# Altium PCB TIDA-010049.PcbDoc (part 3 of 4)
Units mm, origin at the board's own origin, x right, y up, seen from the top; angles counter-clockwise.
Board outline 75 x 60 mm, 4 copper layers (Top Layer, GND, Supply, Bottom Layer), stack 1.565 mm thick; 309 components, 186 nets, 995 pads, 362 vias.
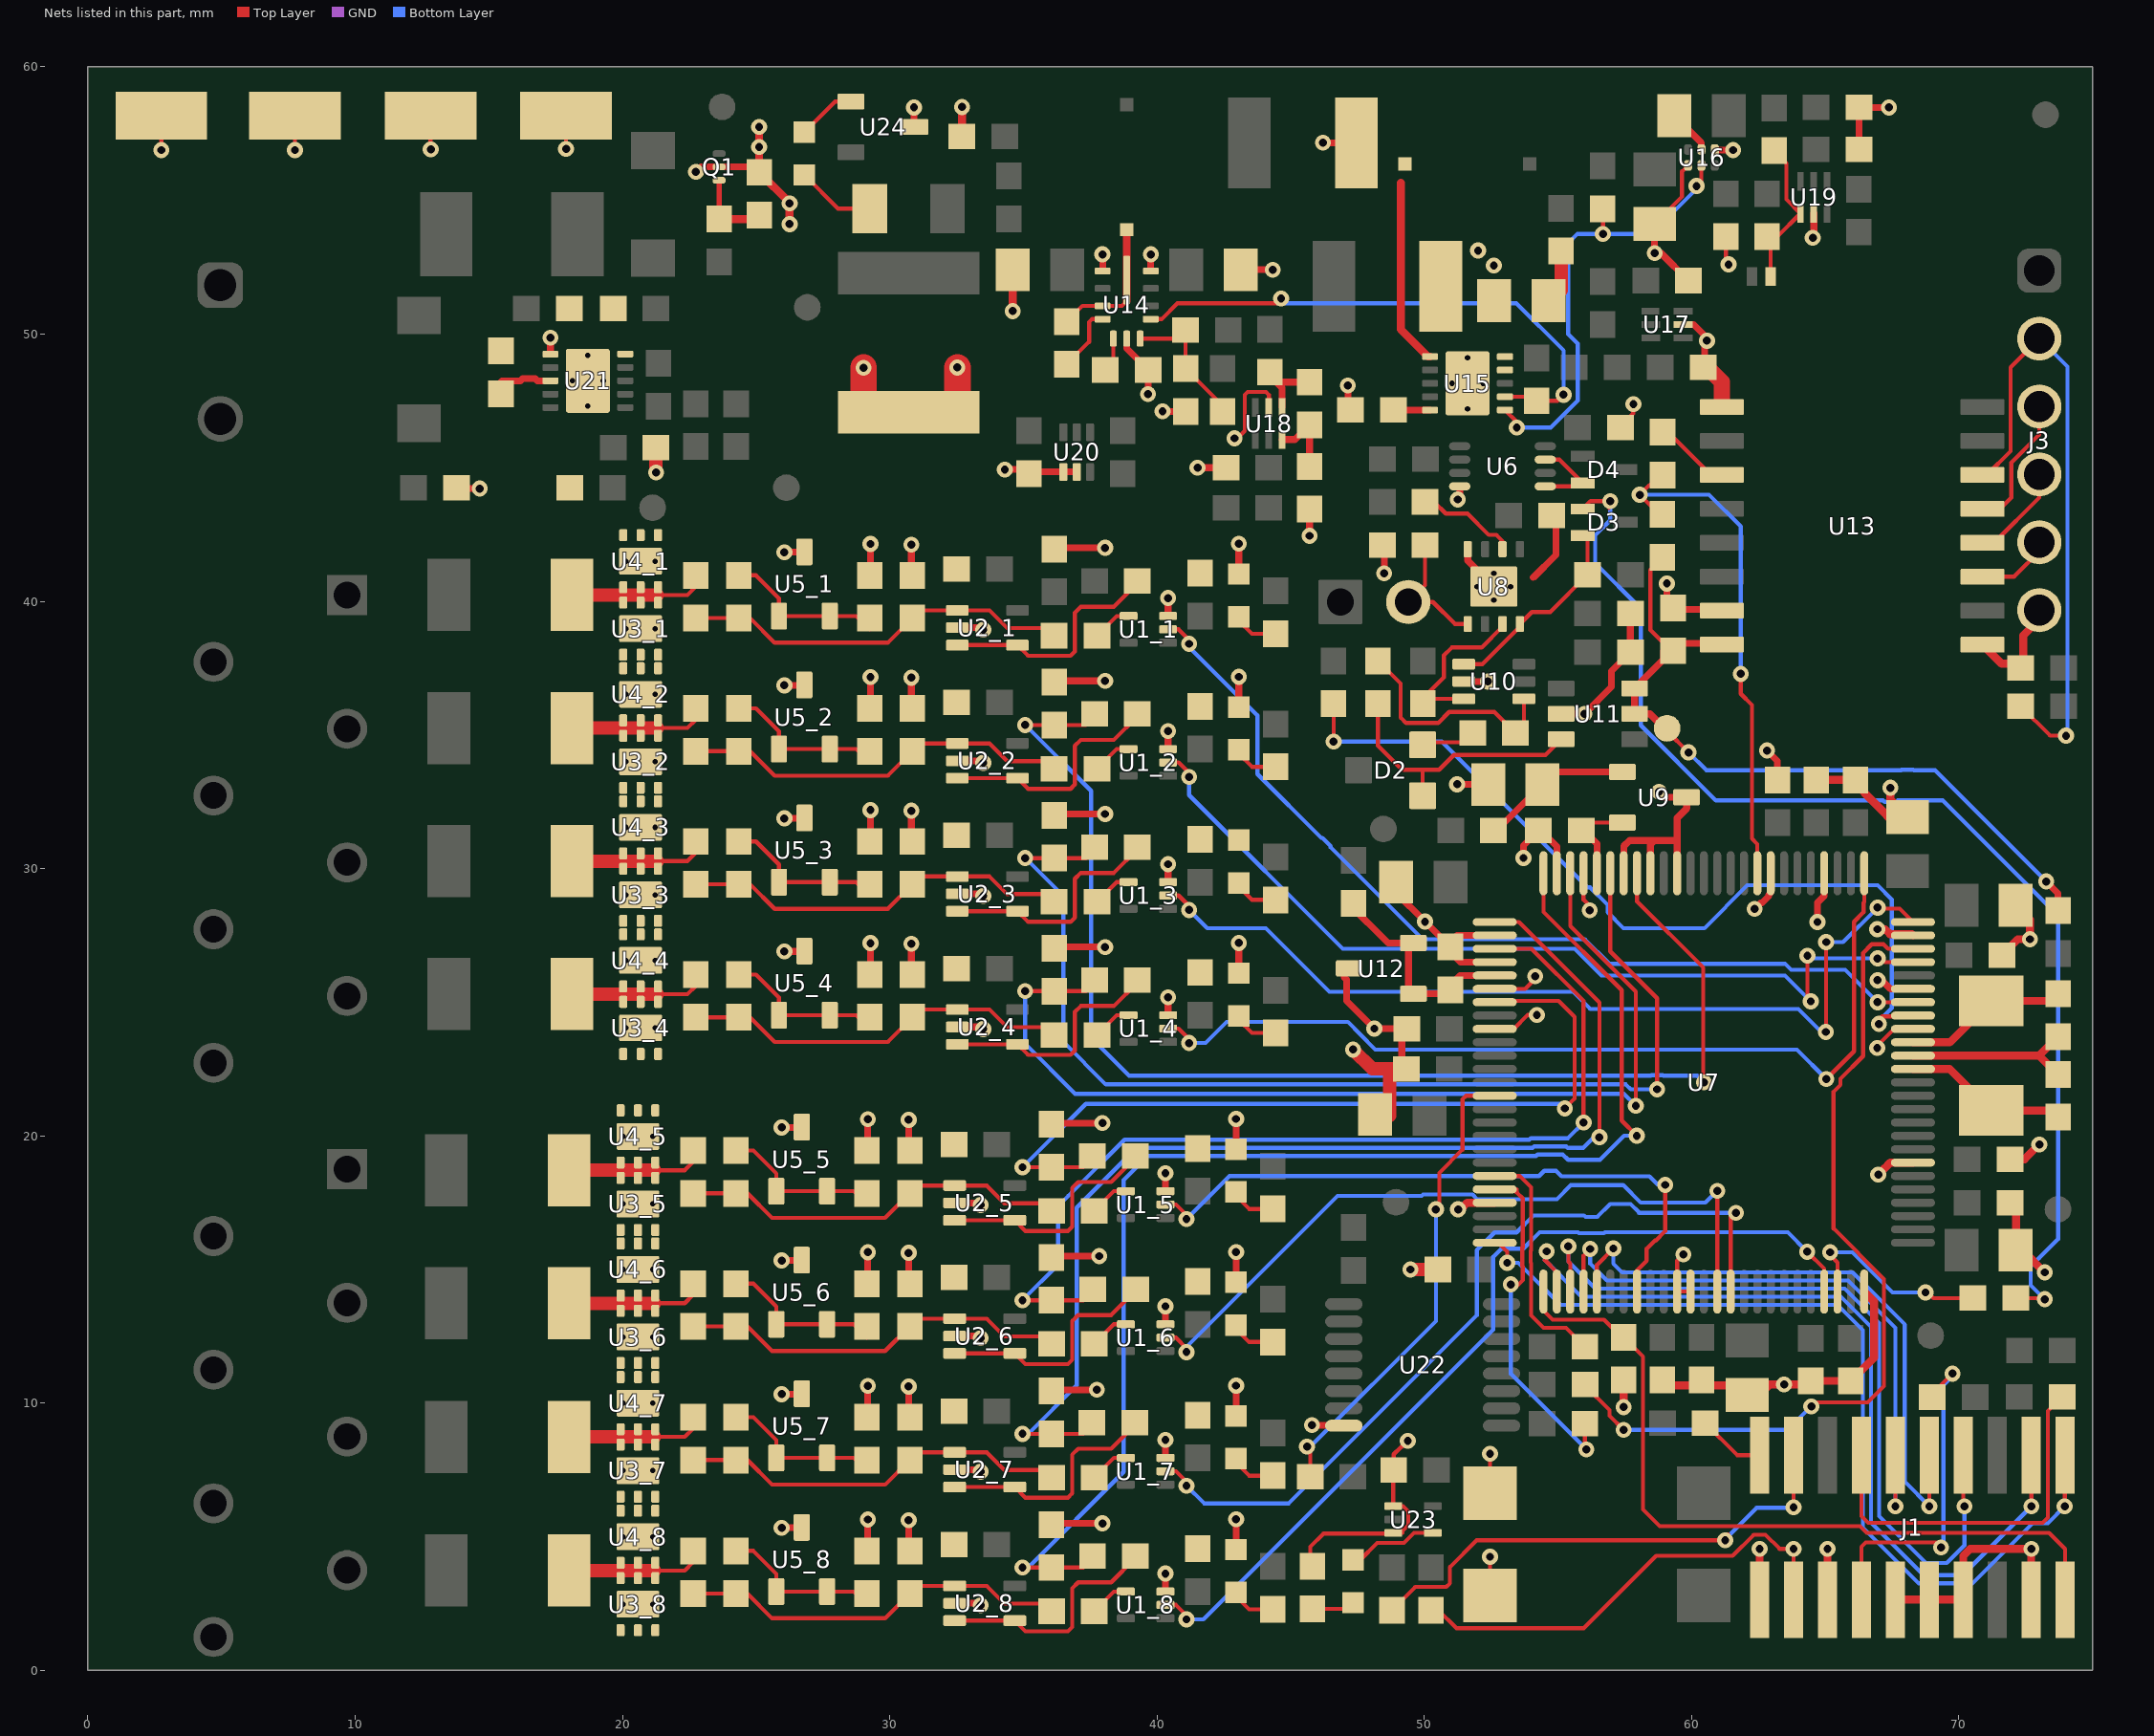
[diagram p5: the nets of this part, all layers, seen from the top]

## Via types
v1: diameter 0.6, hole 0.3, Top Layer to Bottom Layer, 318 vias
v2: diameter 0.5, hole 0.2, Top Layer to Bottom Layer, 44 vias

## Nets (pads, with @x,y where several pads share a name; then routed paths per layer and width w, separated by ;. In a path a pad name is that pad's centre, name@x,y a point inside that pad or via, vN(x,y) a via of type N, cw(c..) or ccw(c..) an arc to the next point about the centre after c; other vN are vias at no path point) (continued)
DI_LOGIC2: C1_2.1 R4_2.2 U7.43 | length 48.5
  Top Layer w0.152: v1(35.07,35.371) C1_2.1@36.152,35.371 37.342,35.371 R4_2.2@37.563,35.592 ; R4_2.2@37.308,35.846 R4_2.2@37.563,35.592 ; R4_2.2@37.667,35.571 37.583,35.571 R4_2.2@37.563,35.592 ; U7.43@57.958,29.825 57.958,28.768 60.429,26.296 60.429,22.028 v1(60.458,22)
  Bottom Layer w0.152: v1@35.277,35.371 v1(35.07,35.371) 37.532,32.909 37.532,23.676 38.958,22.25 58.471,22.25 58.489,22.268 58.927,22.268 58.945,22.25 60.208,22.25 v1(60.458,22)
DI_LOGIC3: C1_3.1 R4_3.2 U7.45 | length 42.5
  Top Layer w0.152: v1(35.07,30.393) C1_3.1@36.152,30.393 37.342,30.393 R4_3.2@37.563,30.614 ; R4_3.2@37.308,30.868 R4_3.2@37.563,30.614 ; R4_3.2@37.667,30.593 37.583,30.593 R4_3.2@37.563,30.614 ; U7.45@56.958,29.825 56.958,26.901 58.708,25.151 v1(58.708,21.74)
  Bottom Layer w0.152: v1@35.277,30.393 v1(35.07,30.393) 36.5,28.963 36.5,23.511 38.085,21.926 57.54,21.926 57.727,21.74 v1(58.708,21.74)
DI_LOGIC4: C1_4.1 R4_4.2 U7.48 | length 38.7
  Top Layer w0.152: v1(35.07,25.414) C1_4.1@36.152,25.414 37.342,25.414 R4_4.2@37.563,25.635 ; R4_4.2@37.308,25.889 R4_4.2@37.563,25.635 ; R4_4.2@37.667,25.614 37.583,25.614 R4_4.2@37.563,25.635 ; U7.48@55.458,29.825 55.458,27.849 57.91,25.396 v1(57.91,21.128)
  Bottom Layer w0.152: v1@35.277,25.414 v1(35.07,25.414) 35.07,23.438 36.934,21.574 57.465,21.574 v1(57.91,21.128)
DI_LOGIC5: C1_5.1 R4_5.2 U7.57 | length 31.5
  Top Layer w0.152: v1(34.969,18.828) C1_5.1@36.052,18.828 37.241,18.828 R4_5.2@37.462,19.049 ; R4_5.2@37.208,19.303 R4_5.2@37.462,19.049 ; R4_5.2@37.566,19.028 37.483,19.028 R4_5.2@37.462,19.049 ; U7.57@52.633,25 52.633,25.052 55.024,25.052 55.626,24.449 55.626,21.397 v1(55.255,21.025)
  Bottom Layer w0.152: v1@35.177,18.828 v1(34.969,18.828) 37.336,21.195 55.085,21.195 v1(55.255,21.025)
DI_LOGIC6: C1_6.1 R4_6.2 U7.53 | length 37
  Top Layer w0.152: v1(34.969,13.85) C1_6.1@36.052,13.85 37.241,13.85 R4_6.2@37.462,14.071 ; R4_6.2@37.208,14.325 R4_6.2@37.462,14.071 ; R4_6.2@37.566,14.05 37.483,14.05 R4_6.2@37.462,14.071 ; U7.53@52.633,27 54.005,27 55.958,25.047 v1(55.958,20.5)
  Bottom Layer w0.152: v1@35.177,13.85 v1(34.969,13.85) 36.302,15.182 36.302,17.372 36.698,17.768 36.698,17.775 36.875,17.952 36.881,17.952 38.784,19.855 53.926,19.855 53.984,19.912 55.37,19.912 v1(55.958,20.5)
DI_LOGIC7: C1_7.1 R4_7.2 U7.51 | length 43.4
  Top Layer w0.152: v1(34.97,8.85) C1_7.1@36.052,8.85 37.241,8.85 R4_7.2@37.462,9.071 ; R4_7.2@37.208,9.325 R4_7.2@37.462,9.071 ; R4_7.2@37.566,9.05 37.483,9.05 R4_7.2@37.462,9.071 ; U7.51@52.633,28 53.537,28 56.55,24.987 v1(56.55,19.95)
  Bottom Layer w0.152: v1(34.97,8.85) 35.177,8.85 37,10.673 37,17.314 39.236,19.55 54.053,19.55 54.11,19.608 55.306,19.608 55.363,19.55 55.941,19.55 56.35,19.958 56.358,19.95 v1(56.55,19.95)
DI_LOGIC8: C1_8.1 R4_8.2 U7.50 | length 50.6
  Top Layer w0.152: v1(34.969,3.85) C1_8.1@36.052,3.85 37.241,3.85 R4_8.2@37.462,4.071 ; R4_8.2@37.208,4.325 R4_8.2@37.462,4.071 ; R4_8.2@37.566,4.05 37.483,4.05 R4_8.2@37.462,4.071 ; U7.50@54.458,29.825 54.458,28.379 57.384,25.453 57.384,20.568 v1(57.948,20.005)
  Bottom Layer w0.152: v1(34.969,3.85) 35.177,3.85 38.75,7.424 38.75,18.345 39.65,19.245 54.179,19.245 54.236,19.303 55.179,19.303 55.379,19.103 56.573,19.103 57.474,20.005 v1(57.948,20.005)
DIAG_CTRL1: U1_1.2 U7.19 | length 35.1
  Top Layer w0.152: U1_1.2@40.415,38.95 40.807,38.95 41.202,38.554 v1(41.202,38.409) ; v1(66.958,25) 67.099,25 U7.19@68.283,25
  Bottom Layer w0.152: v1(41.202,38.409) 41.202,38.287 43.758,35.731 43.758,33.533 46.146,31.145 46.187,31.145 46.497,30.836 46.497,30.795 49.936,27.355 56.003,27.355 56.917,26.441 63.491,26.441 63.721,26.211 65.747,26.211 v1(66.958,25)
DIAG_CTRL2: U1_2.2 U7.22 | length 34.2
  Top Layer w0.152: U1_2.2@40.415,33.971 40.807,33.971 41.202,33.576 v1(41.202,33.43) ; v1(64.333,26.739) 64.333,25.156 v1(64.458,25.031) ; v1(66.958,26.639) 67.077,26.639 67.216,26.5 U7.22@68.283,26.5
  Bottom Layer w0.152: v1(41.202,33.43) 41.202,32.751 46.953,27 55.626,27 56.626,26 63.489,26 v1(64.458,25.031) ; v1@64.208,26.739 v1(64.333,26.739) 64.458,26.739 64.558,26.639 v1(66.958,26.639)
DIAG_CTRL3: U1_3.2 U7.25 | length 34.2
  Top Layer w0.152: U1_3.2@40.415,28.993 40.807,28.993 41.202,28.597 v1(41.202,28.452) ; v1(65.023,23.889) 65.032,23.898 v1(65.032,27.25) ; v1@66.958,28.5 67.783,28.5 U7.25@68.283,28
  Bottom Layer w0.152: v1(41.202,28.452) 41.882,27.772 44.07,27.772 46.453,25.39 55.568,25.39 56.208,24.75 63.991,24.75 64.852,23.889 v1(65.023,23.889) ; v1(65.032,27.25) 65.667,27.25 v1(66.958,28.541)
DIAG_CTRL4: U1_4.2 U7.26 | length 34.4
  Top Layer w0.152: U1_4.2@40.415,24.014 40.807,24.014 41.202,23.619 v1(41.202,23.473) ; v1(65.039,22.128) 66.073,23.162 66.073,28.01 66.429,28.366 66.429,28.719 66.458,28.748 U7.26@66.458,29.825
  Bottom Layer w0.152: v1(41.202,23.473) 41.819,23.473 42.605,24.259 47.141,24.259 47.6,23.8 47.6,23.795 48.167,23.229 63.938,23.229 v1(65.039,22.128)
DIAG_CTRL5: U1_5.2 U7.83 | length 24.4
  Top Layer w0.152: U1_5.2@40.315,17.428 40.706,17.428 41.102,17.033 v1(41.102,16.887) ; U7.83@57.958,14.175 57.958,14.966 58.323,15.331 58.317,15.337 58.317,15.773 58.625,16.081 58.658,16.081 59.009,16.432 v1(59.009,18.165)
  Bottom Layer w0.152: v1(41.102,16.887) 42.708,18.494 54.289,18.494 54.489,18.693 54.927,18.693 55.13,18.491 58.419,18.491 58.745,18.165 v1(59.009,18.165)
DIAG_CTRL6: U1_6.2 U7.89 | length 28
  Top Layer w0.152: U1_6.2@40.315,12.45 40.706,12.45 41.102,12.054 v1(41.102,11.909) ; U7.89@60.958,14.175 v1(60.958,17.942)
  Bottom Layer w0.152: v1(41.102,11.909) 41.102,12.099 46.757,17.754 49.899,17.754 49.95,17.805 51.806,17.805 51.979,17.632 54.958,17.632 55.48,18.154 57.442,18.154 58.096,17.5 60.516,17.5 v1(60.958,17.942)
DIAG_CTRL7: U1_7.2 U7.90 | length 31.1
  Top Layer w0.152: U1_7.2@40.315,7.45 40.707,7.45 41.102,7.055 v1(41.102,6.909) ; U7.90@61.458,14.175 v1@61.458,17.077
  Bottom Layer w0.152: v1(41.102,6.909) 41.761,6.25 44.932,6.25 51.962,13.28 51.962,15.721 52.629,16.388 53.448,16.388 54.082,17.022 55.973,17.022 56.032,16.963 56.468,16.963 56.955,17.45 57.718,17.45 58.026,17.142 58.026,17.115 v1(61.66,17.115)
DIAG_CTRL8: U1_8.2 U7.97 | length 34
  Top Layer w0.152: U1_8.2@40.315,2.45 40.706,2.45 41.102,2.055 v1(41.102,1.909) ; v1(64.323,15.666) 64.958,15.031 U7.97@64.958,14.175
  Bottom Layer w0.152: v1(41.102,1.909) 41.737,1.909 52.571,12.743 52.571,15.469 52.881,15.779 53.7,15.779 54.315,16.394 55.746,16.394 55.782,16.358 56.718,16.358 56.754,16.394 63.595,16.394 v1(64.323,15.666)
DVDD: C28.1 J3.6 U13.1 | length 4.2
  Top Layer w0.3: U13.1@70.883,38.38 71.595,37.668 72.408,37.668 72.408,38.726 J3.6@73.327,39.645
GND: C1_1.2 C1_2.2 C1_3.2 C1_4.2 C1_5.2 C1_6.2 C1_7.2 C1_8.2 C2_1.2 C2_2.2 C2_3.2 C2_4.2 C2_5.2 C2_6.2 C2_7.2 C2_8.2 C3_1.2 C3_2.2 C3_3.2 C3_4.2 C3_5.2 C3_6.2 C3_7.2 C3_8.2 C4_1.2 C4_2.2 C4_3.2 C4_4.2 C4_5.2 C4_6.2 C4_7.2 C4_8.2 C5.2 C6.2 C7.2 C8.2 C9.2 C10.2 C11.2 C12.2 C13.2 C14.2 C15.2 C16.2 C17.2 C18.2 C19.2 C20.2 C21.2 C22.2 C23.2 C24.2 C25.2 C26.2 C27.2 C29.2 C30.2 C33.2 C35.2 C36.2 C37.2 C39.2 C40.2 C41.2 C42.2 C43.2 C44.2 C45.2 C46.2 C47.2 C48.2 C49.2 C50.2 C52.2 C53.2 D1_1.1 D1_2.1 D1_3.1 D1_4.1 D1_5.1 D1_6.1 D1_7.1 D1_8.1 J1.4 J1.8 J1.10 J1.12 J1.16 J1.20 Q1.2@23.616,56.25 R7_1.1 R7_2.1 R7_3.1 R7_4.1 R7_5.1 R7_6.1 R7_7.1 R7_8.1 R17.1 R20.1 R33.2 R34.2 R36.2 R46.2 R47.2 R48.2 R62.2 R64.1 S1.1 S2.1 TP11.1 TP12.1 TP13.1 TP14.1 U1_1.3 U1_2.3 U1_3.3 U1_4.3 U1_5.3 U1_6.3 U1_7.3 U1_8.3 U2_1.2 U2_2.2 U2_3.2 U2_4.2 U2_5.2 U2_6.2 U2_7.2 U2_8.2 U3_1.1 U3_1.2 U3_1.3 U3_1.7@20.681,38.975 U3_2.1 U3_2.2 U3_2.3 U3_2.7@20.681,33.996 U3_3.1 U3_3.2 U3_3.3 U3_3.7@20.681,29.018 U3_4.1 U3_4.2 U3_4.3 U3_4.7@20.681,24.039 U3_5.1 U3_5.2 U3_5.3 U3_5.7@20.581,17.453 U3_6.1 U3_6.2 U3_6.3 U3_6.7@20.581,12.475 U3_7.1 U3_7.2 U3_7.3 U3_7.7@20.581,7.475 U3_8.1 U3_8.2 U3_8.3 U3_8.7@20.581,2.475 U4_1.1 U4_1.2 U4_1.3 U4_1.7@20.681,41.5 U4_2.1 U4_2.2 U4_2.3 U4_2.7@20.681,36.521 U4_3.1 U4_3.2 U4_3.3 U4_3.7@20.681,31.543 U4_4.1 U4_4.2 U4_4.3 U4_4.7@20.681,26.564 U4_5.1 U4_5.2 U4_5.3 U4_5.7@20.581,19.978 U4_6.1 U4_6.2 U4_6.3 U4_6.7@20.581,15 U4_7.1 U4_7.2 U4_7.3 U4_7.7@20.581,10 U4_8.1 U4_8.2 U4_8.3 U4_8.7@20.581,5 U5_1.3 U5_2.3 U5_3.3 U5_4.3 U5_5.3 U5_6.3 U5_7.3 U5_8.3 U6.4 U7.7 U7.17 U7.20 U7.24 U7.29 U7.33 U7.40 U7.42 U7.44 U7.47 U7.49 U7.52 U7.54 U7.56 U7.59 U7.72 U7.86 U7.87 U7.100 U8.4 U8.9 U9.3 U10.2 U11.2 U12.3 U13.9 U13.15 U14.1 U14.6 U14.11 U15.9 U15.10 U15.11 U16.1 U16.4 U17.5 U18.5 U19.5 U20.1 U20.2 U21.6 U22.8 U23.1 U23.3 U24.3 | length 231.9
  Top Layer w0.152: v1(2.75,56.881) TP11.1@2.75,58.174 ; v1(7.75,56.881) TP12.1@7.75,58.174 ; TP13.1@12.822,58.17 12.822,56.918 v1(12.833,56.907) ; v1(17.891,56.93) TP14.1@17.891,58.174 ; R36.2@24.916,56.25 R36.2@25.116,56.05 ; v1(42.902,46.098) 43.008,46.098 43.287,46.376 43.287,47.729 43.392,47.834 44.075,47.834 44.183,47.726 U18.5@44.183,47.255 ; R64.1@45.818,3.9 45.733,3.985 45.733,4.624 46.225,5.116 48.839,5.116 U23.3@48.839,5.147 49.187,5.147 49.187,5.268 49.239,5.268 49.402,5.431 49.402,5.948 49.203,6.147 U23.1@48.839,6.147 48.839,7.272 48.854,7.287 C53.2@48.854,7.5 48.854,8.086 v1(49.382,8.591) ; S2.1@52.458,2.95 v1(52.458,4.25) ; S1.1@52.458,6.625 v1(52.458,8.103) ; U7.59@52.633,24 53.343,24 53.869,24.526 v1(54.21,24.526) ; U7.56@52.633,25.5 53.771,25.5 54.15,25.879 v1(54.15,25.973) ; U7.47@55.958,29.825 55.958,28.83 56.191,28.597 v1@56.175,28.581 ; C33.2@57.258,46.47 57.814,47.026 57.814,47.089 57.823,47.098 v1(57.823,47.376) ; C44.2@58.616,54.123 59.642,55.149 59.642,56.082 U16.4@59.866,56.306 ; v1(59.689,15.565) 59.458,15.334 U7.86@59.458,14.175 U7.87@59.958,14.175 ; C41.2@61.281,53.775 C41.2@61.281,53.646 61.281,52.705 v1(61.382,52.604) ; v1(66.942,23.289) 66.942,23.373 67.569,24 U7.17@68.283,24
  Top Layer w0.25: v1(22.75,56.067) 22.933,56.25 Q1.2@23.616,56.25 R36.2@24.916,56.25
  Top Layer w0.254: TP11.1@2.208,57.55 TP11.1@2.25,57.508 ; C50.2@13.606,44.217 v1(14.658,44.217) ; U21.6@17.308,49.25 v1(17.308,49.865) ; v1@25.972,5.35 v1(25.958,5.336) 26.694,5.336 U5_8.3@26.708,5.35 ; v1@25.972,10.35 v1(25.958,10.336) 26.695,10.336 U5_7.3@26.708,10.35 ; v1@25.972,15.35 v1(25.958,15.336) 26.694,15.336 U5_6.3@26.708,15.35 ; v1@25.972,20.328 v1(25.958,20.315) 26.694,20.315 U5_5.3@26.708,20.328 ; v1@26.072,26.914 v1(26.058,26.901) 26.795,26.901 U5_4.3@26.808,26.914 ; v1@26.072,31.893 v1(26.058,31.879) 26.795,31.879 U5_3.3@26.808,31.893 ; v1@26.072,36.871 v1(26.058,36.858) 26.795,36.858 U5_2.3@26.808,36.871 ; v1@26.072,41.85 v1(26.058,41.836) 26.795,41.836 U5_1.3@26.808,41.85 ; R7_8.1@29.15,4.471 29.18,4.501 v1(29.18,5.647) ; R7_7.1@29.15,9.471 29.18,9.501 v1(29.18,10.647) ; R7_6.1@29.15,14.471 29.18,14.501 v1(29.18,15.646) ; R7_5.1@29.15,19.449 29.18,19.479 v1(29.18,20.625) ; R7_4.1@29.251,26.035 29.281,26.065 v1(29.281,27.211) ; R7_3.1@29.251,31.014 29.281,31.044 v1(29.281,32.189) ; R7_2.1@29.251,35.992 29.281,36.022 v1(29.281,37.168) ; R7_1.1@29.251,40.971 29.281,41.001 v1(29.281,42.146) ; v1(30.708,5.622) 30.708,4.513 C2_8.2@30.75,4.471 ; v1(30.708,10.622) 30.708,9.513 C2_7.2@30.75,9.471 ; v1(30.708,15.621) 30.708,14.513 C2_6.2@30.75,14.471 ; v1(30.708,20.6) 30.708,19.491 C2_5.2@30.75,19.449 ; v1(30.808,27.186) 30.808,26.077 C2_4.2@30.85,26.035 ; v1(30.808,32.164) 30.808,31.056 C2_3.2@30.85,31.014 ; v1(30.808,37.143) 30.808,36.034 C2_2.2@30.85,35.992 ; v1(30.808,42.121) 30.808,41.013 C2_1.2@30.85,40.971 ; v1(30.908,58.477) 30.908,57.792 U24.3@30.95,57.75 ; U2_8.2@32.429,2.511 33.324,2.511 v1(33.4,2.436) ; U2_6.2@32.429,12.511 33.324,12.511 v1(33.4,12.435) ; U2_5.2@32.429,17.49 33.324,17.49 v1(33.4,17.414) ; U2_7.2@32.429,7.511 33.325,7.511 v1(33.4,7.436) ; U2_4.2@32.529,24.076 33.425,24.076 v1(33.501,24) ; U2_3.2@32.529,29.054 33.425,29.054 v1(33.501,28.978) ; U2_2.2@32.529,34.033 33.425,34.033 v1(33.501,33.957) ; U2_1.2@32.529,39.011 33.425,39.011 v1(33.501,38.935) ; v1(34.304,44.93) 35.058,44.93 C48.2@35.208,44.78 35.268,44.84 U20.1@36.494,44.84 U20.2@36.994,44.84 ; C1_8.2@36.052,5.45 36.102,5.5 v1(37.958,5.5) ; C1_7.2@36.052,10.45 36.102,10.5 v1(37.75,10.5) ; C1_5.2@36.052,20.428 36.102,20.478 v1(37.958,20.478) ; C1_6.2@36.102,15.5 v1@37.75,15.5 ; C1_4.2@36.152,27.014 36.202,27.064 v1(38.058,27.064) ; C1_3.2@36.152,31.993 36.202,32.043 v1(38.058,32.043) ; C1_2.2@36.152,36.971 36.202,37.021 v1(38.058,37.021) ; C1_1.2@36.152,41.95 36.202,42 v1(38.058,42) ; v1(37.958,52.979) 37.966,52.987 U14.1@37.966,52.356 ; U14.6@38.866,49.831 38.866,49.455 C42.2@39.666,48.655 v1(39.666,47.75) ; U14.11@39.766,52.356 v1(39.766,52.979) ; v1(40.206,47.105) R33.2@41.183,47.105 ; U1_8.3@40.315,2.95 v1(40.315,3.621) ; U1_7.3@40.315,7.95 v1(40.315,8.621) ; U1_6.3@40.315,12.95 v1(40.315,13.621) ; U1_5.3@40.315,17.928 v1(40.315,18.6) ; U1_4.3@40.415,24.514 v1(40.415,25.185) ; U1_3.3@40.415,29.493 v1(40.415,30.164) ; U1_2.3@40.415,34.471 v1(40.415,35.142) ; U1_1.3@40.415,39.45 v1(40.415,40.121) ; v1(41.516,45) C46.2@42.583,45 ; D1_8.1@42.958,4.522 v1(42.958,5.654) ; D1_7.1@42.958,9.522 v1(42.958,10.654) ; D1_6.1@42.958,14.521 v1(42.958,15.653) ; D1_5.1@42.958,19.5 v1(42.958,20.632) ; D1_4.1@43.058,26.086 v1(43.058,27.218) ; D1_2.1@43.058,36.043 v1(43.058,37.175) ; D1_1.1@43.059,41.021 v1(43.058,42.153) ; C37.2@43.132,52.405 v1(44.33,52.405) ; v1(45.708,42.45) R47.2@45.708,43.45 ; v1(45.793,9.175) U22.8@46.969,9.175 ; v1(46.208,57.158) C39.2@47.458,57.158 C39.2@46.833,56.533 ; U12.3@47.008,26.264 47.008,25.927 47.088,25.847 47.088,25.055 v1(48.129,24.014) 49.158,24.014 C14.2@49.158,22.506 ; v1(47.141,48.075) 47.141,47.261 R34.2@47.239,47.164 ; R17.1@48.429,42.107 48.429,41.86 48.5,41.789 v1(48.5,41.05) ; C19.2@48.942,29.493 48.942,29.097 v1(50.025,28.014) 50.791,27.248 C27.2@50.791,27.064 ; v1(51.227,33.154) 51.235,33.146 C17.2@52.391,33.146 ; v1(51.25,43.808) 51.325,43.883 U6.4@51.325,44.3 ; U10.2@51.475,37 v1(52.382,37) ; U8.4@51.625,41.95 51.625,41.525 U8.9@52.6,40.55 ; U7.54@52.633,26.5 51.355,26.5 C27.2@50.791,27.064 ; U7.52@52.633,27.5 51.227,27.5 C27.2@50.791,27.064 ; v1(53.708,30.398) 53.708,30.858 C18.2@54.27,31.419 ; 54.074,40.888 54.925,41.74 C5.2@54.925,43.15 ; C18.2@54.236,31.453 54.283,31.5 54.958,30.825 U7.49@54.958,29.825 ; U11.2@55.118,35.79 v1(55.993,35.79) 57,36.798 57,37.392 C26.2@57.708,38.1 C30.2@57.708,39.548 ; U7.44@57.458,29.825 57.458,30.834 57.674,31.05 58.608,31.05 ; U7.42@58.458,29.825 58.458,30.9 58.608,31.05 ; C44.2@58.616,54.123 v1(58.616,53.03) 58.853,53.03 C45.2@59.883,52 ; v1(58.783,32.877) 58.783,32.76 58.876,32.668 U9.3@59.808,32.668 59.816,32.66 59.816,32.25 59.458,31.892 59.458,31.05 ; v1(59.073,40.665) 59.073,39.985 C29.2@59.308,39.75 ; C29.2@59.308,39.701 U13.15@61.083,39.701 ; U7.40@59.458,29.825 59.458,31.05 ; U17.5@59.683,50.355 60.07,50.355 60.485,49.94 R46.2@60.485,48.857 ; U16.1@60.866,56.881 v1(61.553,56.881) ; v1(62.358,28.49) 62.588,28.721 62.636,28.721 62.887,28.972 62.887,29.02 62.958,29.09 U7.33@62.958,29.825 ; v1(62.823,34.418) 63.208,34.033 C13.2@63.208,33.569 ; v1(64.531,53.599) 64.573,53.641 U19.5@64.573,54.513 ; v1(64.708,28) 64.708,28.727 64.958,28.977 U7.29@64.958,29.825 ; C47.2@66.258,56.906 R48.2@66.258,58.477 v1(67.378,58.477) ; v1@67.041,25.896 67.437,25.5 U7.20@68.283,25.5 ; 58.608,31.05 59.458,31.05
  Top Layer w0.3: v1(25.116,57.75) v1(25.116,57) R36.2@25.116,56.05 26.254,54.912 v1(26.254,54.889) v1(26.254,54.114) ; R62.2@32.704,57.397 v1(32.704,58.496) ; v1(34.6,50.858) C36.2@34.6,52.405 ; v1@51.382,17.276 51.606,17.5 U7.72@52.633,17.5 ; v1(57.458,9.853) R20.1@57.458,10.861 ; C24.2@58.958,10.663 62.029,10.663 62.458,10.234 62.924,10.7 v1(63.458,10.7) C25.2@64.458,10.7 ; J1.20@62.543,2.645 v1(62.543,4.55) ; C25.2@64.458,10.832 C16.2@65.958,10.832 66.821,11.696 66.821,13.812 U7.100@66.458,14.175 ; C12.2@64.458,33.318 C12.2@64.658,33.318 65.999,33.318 66.06,33.255 67.704,31.572 C7.2@67.708,31.568 ; J1.16@65.083,2.645 v1(65.083,4.55) ; v1(66.948,27.732) 67.236,27.732 67.421,27.548 68.235,27.548 U7.24@68.283,27.5 ; v1(66.983,18.55) 67.209,18.776 67.211,18.776 67.435,19 U7.7@68.283,19 ; v1(67.437,33.021) 67.437,32.571 C7.2@68.075,31.934 C7.2@68.075,31.475 ; J1.12@67.623,2.338 J1.12@67.623,2.645 J1.10@68.893,2.645 J1.8@70.163,2.645 70.163,4.286 70.427,4.55 v1(72.708,4.55) 72.703,4.545 J1.4@72.703,2.645 ; C11.2@71.608,26.764 72.199,27.355 v1(72.658,27.355) 72.658,28.091 C6.2@72.124,28.625 ; C21.2@71.908,17.5 72.142,17.266 72.142,15.807 C20.2@72.224,15.725 ; C10.2@71.908,19.125 72.455,19.125 v1(73.008,19.678) ; C20.2@72.124,15.725 C20.2@72.224,15.725 ; C20.2@72.474,15.475 C20.2@72.224,15.725 ; v1(73.208,14.892) 72.375,15.725 C20.2@72.224,15.725
  Top Layer w0.5: v1(21.258,44.823) C49.2@21.258,45.75 ; v1(47.333,23.229) 48.055,22.506 48.791,22.506 ; C8.2@48.708,20.75 48.708,22.423 48.791,22.506 ; C14.2@49.329,22.506 49.158,22.506 48.791,22.506 ; v1(49.479,15) C52.2@50.508,15
  Top Layer w0.6: R46.2@60.485,48.857 61.133,48.21 U13.9@61.133,47.27
  Top Layer w1: C35.2@29.022,47.164 v1(29.022,48.74) ; C35.2@32.529,47.075 v1(32.529,48.75)
  GND w0.152: v1@56.175,28.557 v1@56.175,28.581
  GND w0.254: v1@37.958,52.75 v1(37.958,52.979)
  GND w0.3: v1@73.008,19.55 v1(73.008,19.678)
  Bottom Layer w0.152: v1@57.711,47.195 57.823,47.307 v1(57.823,47.376)
  other v1: 37.837,15.502 51.263,17.25 66.958,25.821 56.184,28.435 60.573,49.75 52.602,52.564 52.009,53.124
  other v2: 20.031,2.475 21.131,2.475 20.031,5 21.131,5 20.031,7.475 21.131,7.475 20.031,10 21.131,10 20.031,12.475 21.131,12.475 20.031,15 21.131,15 20.031,17.453 21.131,17.453 20.031,19.978 21.131,19.978 20.131,24.039 21.231,24.039 20.131,26.564 21.231,26.564 20.131,29.018 21.231,29.018 20.131,31.543 21.231,31.543 20.131,33.996 21.231,33.996 20.131,36.521 21.231,36.521 20.131,38.975 21.231,38.975 52.6,40.05 51.975,40.55 53.225,40.55 52.6,41.05 20.131,41.5 21.231,41.5 51.616,47.205 51.041,48.155 52.191,48.155 51.616,49.105
JTAG_EMU0: J1.13 R11.1 | length 14.2
  Top Layer w0.152: J1.13@66.353,8.055 66.353,5.775 66.606,5.522 73.134,5.522 73.327,5.715 73.327,9.703 R11.1@73.858,10.234
JTAG_EMU1: J1.14 R12.1 | length 13
  Top Layer w0.152: J1.14@66.353,2.645 66.353,4.623 66.517,4.787 69.143,4.787 v1(69.33,4.6) ; R12.1@69.005,10.225 68.941,10.289 69.757,11.105 v1(69.763,11.105)
  Bottom Layer w0.152: v1(69.33,4.6) 69.422,4.692 69.422,10.676 69.763,11.018 v1(69.763,11.105)
JTAG_EMU2: J1.17 R10.1 | length 19.3
  Top Layer w0.152: R10.1@48.791,2.25 49.662,3.121 50.819,3.121 50.953,3.255 50.953,3.864 51.956,4.867 v1(61.256,4.867) 61.256,4.979 v1@61.368,5.091 ; v1(63.813,6.1) J1.17@63.813,8.055
  Bottom Layer w0.152: v1(61.256,4.867) 61.216,4.867 62.431,6.082 63.795,6.082 v1(63.813,6.1)
JTAG_EMU3: J1.18 R13.1 | length 17.4
  Top Layer w0.152: R13.1@50.249,2.25 50.532,2.25 51.203,1.579 55.962,1.579 58.67,4.286 61.532,4.286 62.324,5.079 62.762,5.079 63.291,4.55 v1(63.813,4.55) J1.18@63.813,2.645
JTAG_EMU4: J1.19 R9.1 | length 2.5
  Top Layer w0.152: R9.1@60.508,9.25 61.703,8.055 J1.19@62.543,8.055
JTAG_RTCK: J1.9 U7.80 | length 23.4
  Top Layer w0.152: U7.80@56.458,14.175 56.458,15.172 v1(57.073,15.787) ; v1(68.893,6.136) J1.9@68.893,8.055
  Bottom Layer w0.152: v1(57.073,15.787) 57.073,15.219 57.399,14.892 66.021,14.892 67.975,12.938 67.975,7.054 v1(68.893,6.136)
JTAG_TCK: J1.11 U7.79 | length 23.3
  Top Layer w0.152: U7.79@55.958,14.175 55.958,15.518 v1(56.208,15.768) ; v1(67.623,6.136) J1.11@67.623,8.055
  Bottom Layer w0.152: v1(56.208,15.768) 56.208,15.211 56.831,14.587 65.856,14.587 67.623,12.821 v1(67.623,6.136)
JTAG_TDI: J1.3 U7.77 | length 32.4
  Top Layer w0.152: v1(54.573,15.679) 54.573,15.422 54.503,15.352 54.958,14.896 U7.77@54.958,14.175 ; J1.3@72.703,8.055 72.708,8.05 v1(72.708,6.136)
  Bottom Layer w0.152: v1(54.573,15.679) 54.573,15.422 54.503,15.352 55.876,13.978 65.584,13.978 66.708,12.854 66.708,5.533 68.678,3.562 70.134,3.562 v1(72.708,6.136)
JTAG_TDO: J1.7 U7.78 | length 29.7
  Top Layer w0.152: v1(55.386,15.865) 55.386,15.295 55.458,15.223 U7.78@55.458,14.175 ; J1.7@70.163,8.055 70.163,6.181 v1(70.208,6.136)
  Bottom Layer w0.152: v1(55.386,15.865) 55.386,15.295 56.398,14.283 65.73,14.283 67.013,13 67.013,5.774 68.766,4.021 69.547,4.021 70.208,4.682 v1(70.208,6.136)
JTAG_TMS: J1.1 U7.75 | length 34.3
  Top Layer w0.152: U7.75@52.633,16 52.766,16 53.1,15.666 v1(53.1,15.25) ; v1(73.958,6.136) 73.958,8.04 J1.1@73.973,8.055
  Bottom Layer w0.152: v1(53.1,15.25) 53.516,15.25 55.093,13.673 65.458,13.673 66.403,12.728 66.403,5.347 68.495,3.255 70.5,3.255 72.75,5.505 73.327,5.505 v1(73.958,6.136)
JTAG_TRST: J1.2 R20.2 U7.76 | length 29.4
  Top Layer w0.152: U7.76@54.458,14.175 54.458,13.465 54.801,13.121 56.724,13.121 R20.2@57.583,12.263 ; R20.2@57.458,12.461 58.179,11.74 58.179,6.021 58.805,5.396 66.301,5.396 66.55,5.147 73.372,5.147 73.973,4.545 J1.2@73.973,2.645
KELVIN: C31.2 C32.2 U7.15 | length 6.7
  Top Layer w0.3: U7.15@68.283,23 72.994,23 ; C31.2@73.708,22.3 73.008,23 72.994,23 ; C32.2@73.708,23.714 72.994,23
LED_CH_FAIL: R63.1 U7.64 | length 17.9
  Top Layer w0.152: v1(45.611,8.375) 45.733,8.253 R63.1@45.733,7.25 ; v1(50.433,17.25) 50.558,17.375 50.558,18.615 51.426,19.483 51.426,21.365 51.561,21.5 U7.64@52.633,21.5
  Bottom Layer w0.152: v1(45.611,8.375) 45.737,8.375 50.433,13.071 v1(50.433,17.25)
LED_CLK: R58.1 U7.71 | length 13.2
  Top Layer w0.152: U7.71@52.633,18 53.447,18 53.447,17.879 53.465,17.879 53.687,17.657 53.687,15.843 53.669,15.826 53.669,15.135 53.687,15.118 53.687,14.604 53.433,14.35 53.266,14.35 v1@53.266,14.382 ; R58.1@56.008,9.225 56.008,8.325 v1(56.062,8.271)
  Bottom Layer w0.152: v1@53.266,14.382 53.239,14.409 53.239,11.093 v1(56.062,8.271)
  other v1: 53.239,14.441
LED_DATA: R59.1 U7.70 | length 8.8
  Top Layer w0.152: U7.70@52.633,18.5 53.564,18.5 53.991,18.073 53.991,15.717 53.974,15.7 53.974,15.262 53.991,15.244 53.991,13.287 54.462,12.817 55.299,12.817 R59.1@56.008,12.107
LED_UPDATE: R57.1 U7.23 | length 32.4
  Top Layer w0.152: R57.1@56.008,10.663 56.929,9.741 56.929,9.529 v1(57.458,9) ; v1@64.506,9.88 v1(64.478,9.88) 64.628,10.03 66.588,10.03 67.198,10.639 67.198,14.646 65.311,16.532 65.311,21.652 65.567,21.909 65.567,22.137 66.413,22.983 66.413,26.842 66.739,27.168 67.177,27.168 67.345,27 U7.23@68.283,27
  Bottom Layer w0.152: v1(57.458,9) 63.598,9 v1(64.478,9.88) 64.525,9.927 64.558,9.927 v1@64.494,9.863
MASK_COLD_RST: R8.1 U7.98 | length 7.6
  Top Layer w0.152: v1(65.18,15.643) 65.18,15.537 65.458,15.258 U7.98@65.458,14.175 ; v1(68.75,14.142) 68.834,14.142 69.046,13.93 R8.1@70.524,13.93
  Bottom Layer w0.152: v1(65.18,15.643) 66.017,15.643 67.518,14.142 v1(68.75,14.142)
MASK_WARM_RST: R25.1 U7.18 | length 32.6
  Top Layer w0.152: v1(46.607,34.75) R25.1@46.607,36.171 ; v1(67.006,24.188) 67.006,24.343 67.134,24.471 68.283,24.471 U7.18@68.283,24.5
  Bottom Layer w0.152: v1(46.607,34.75) 50.65,34.75 56.1,29.3 56.201,29.3 56.855,28.645 56.855,28.367 57.45,27.772 60.481,27.772 62.083,29.374 66.958,29.374 67.487,28.845 67.487,25.57 67.486,24.781 67.006,24.3 v1(67.006,24.188)
MASTER_SPI_CLK: J3.4 U13.4 | length 3.7
  Top Layer w0.152: U13.4@70.883,42.19 71.313,42.19 73.008,43.885 J3.4@73.008,44.75
MASTER_SPI_CS: J3.5 U13.3 | length 2.7
  Top Layer w0.152: U13.3@70.883,40.92 72.063,40.92 J3.5@73.112,41.969
MASTER_SPI_MISO: J3.2 R28.1 U13.6 | length 23.5
  Top Layer w0.152: U13.6@70.883,44.73 71.048,44.73 71.934,45.616 71.934,48.756 J3.2@73.008,49.83 ; R28.1@72.312,36.071 73.412,34.971 v1(74.008,34.971)
  Bottom Layer w0.152: J3.2@73.008,49.83 74.059,48.779 74.059,35.023 v1(74.008,34.971)
MASTER_SPI_MOSI: J3.3 U13.5 | length 5.1
  Top Layer w0.152: U13.5@70.883,43.46 71.537,43.46 71.957,43.88 71.957,45.185 73.008,46.237 J3.3@73.008,47.29
NetC2_1_1: C2_1.1 R1_1.1 R3_1.1 R5_1.2 U2_1.1 | length 14.7
  Top Layer w0.152: R3_1.1@22.748,39.371 R5_1.2@24.35,39.371 24.777,39.371 25.698,38.45 26.808,38.45 29.93,38.45 C2_1.1@30.85,39.371 31.141,39.661 U2_1.1@32.529,39.661 33.731,39.661 34.393,39 35.866,39 R1_1.1@36.152,38.714
NetC2_2_1: C2_2.1 R1_2.1 R3_2.1 R5_2.2 U2_2.1 | length 14.7
  Top Layer w0.152: R3_2.1@22.748,34.392 R5_2.2@24.35,34.392 24.777,34.392 25.698,33.471 26.808,33.471 29.93,33.471 C2_2.1@30.85,34.392 31.141,34.683 U2_2.1@32.529,34.683 33.731,34.683 34.393,34.021 35.866,34.021 R1_2.1@36.152,33.735
NetC2_3_1: C2_3.1 R1_3.1 R3_3.1 R5_3.2 U2_3.1 | length 14.7
  Top Layer w0.152: R3_3.1@22.748,29.414 R5_3.2@24.35,29.414 24.777,29.414 25.698,28.493 26.808,28.493 29.93,28.493 C2_3.1@30.85,29.414 31.141,29.704 U2_3.1@32.529,29.704 33.731,29.704 34.393,29.043 35.866,29.043 R1_3.1@36.152,28.757
NetC2_4_1: C2_4.1 R1_4.1 R3_4.1 R5_4.2 U2_4.1 | length 14.7
  Top Layer w0.152: R3_4.1@22.748,24.435 R5_4.2@24.35,24.435 24.777,24.435 25.698,23.514 26.808,23.514 29.93,23.514 C2_4.1@30.85,24.435 31.141,24.726 U2_4.1@32.529,24.726 33.731,24.726 34.393,24.064 35.866,24.064 R1_4.1@36.152,23.778
NetC2_5_1: C2_5.1 R1_5.1 R3_5.1 R5_5.2 U2_5.1 | length 14.7
  Top Layer w0.152: R3_5.1@22.647,17.849 R5_5.2@24.25,17.849 24.676,17.849 25.597,16.928 26.708,16.928 29.829,16.928 C2_5.1@30.75,17.849 31.041,18.14 U2_5.1@32.429,18.14 33.631,18.14 34.292,17.478 35.765,17.478 R1_5.1@36.052,17.192
NetC2_6_1: C2_6.1 R1_6.1 R3_6.1 R5_6.2 U2_6.1 | length 14.7
  Top Layer w0.152: R3_6.1@22.647,12.871 R5_6.2@24.25,12.871 24.676,12.871 25.597,11.95 26.708,11.95 29.829,11.95 C2_6.1@30.75,12.871 31.041,13.161 U2_6.1@32.429,13.161 33.631,13.161 34.292,12.5 35.765,12.5 R1_6.1@36.052,12.214
NetC2_7_1: C2_7.1 R1_7.1 R3_7.1 R5_7.2 U2_7.1 | length 14.7
  Top Layer w0.152: R3_7.1@22.647,7.871 R5_7.2@24.25,7.871 24.677,7.871 25.598,6.95 26.708,6.95 29.829,6.95 C2_7.1@30.75,7.871 31.041,8.161 U2_7.1@32.429,8.161 33.631,8.161 34.293,7.5 35.766,7.5 R1_7.1@36.052,7.214
NetC2_8_1: C2_8.1 R1_8.1 R3_8.1 R5_8.2 U2_8.1 | length 14.7
  Top Layer w0.152: R3_8.1@22.647,2.871 R5_8.2@24.25,2.871 24.676,2.871 25.597,1.95 26.708,1.95 29.829,1.95 C2_8.1@30.75,2.871 31.041,3.161 U2_8.1@32.429,3.161 33.631,3.161 34.292,2.5 35.765,2.5 R1_8.1@36.052,2.214
NetC17_1: C17.1 R18.2 U9.1 | length 5.6
  Top Layer w0.254: R18.2@52.666,31.543 52.82,31.543 C17.1@54.423,33.146 54.895,33.618 U9.1@57.408,33.618
NetC18_1: C18.1 U7.46 U9.2 | length 3.5
  Top Layer w0.152: C18.1@55.883,31.5 56.101,31.718 U9.2@57.408,31.718
  Top Layer w0.254: C18.1@55.883,31.5 56.458,30.925 U7.46@56.458,29.825
NetC27_1: C27.1 R23.1 U7.55 U12.1 U12.2 | length 8.3
  Top Layer w0.254: R23.1@47.158,28.7 48.644,27.214 49.408,27.214 49.408,25.314 U12.1@49.589,25.314 50.641,25.314 51.327,26 U7.55@52.633,26
NetC29_1: C29.1 R24.1 R26.2 TP8.1 U11.5 U11.6 U13.16 | length 28.2
  Top Layer w0.152: R26.2@58.933,41.65 58.458,41.175 58.458,38.931 C29.1@59.098,38.29 ; TP8.1@59.083,35.146 v1(59.883,34.346)
  Top Layer w0.254: TP8.1@59.083,35.146 58.439,35.79 U11.5@57.868,35.79 U11.6@57.868,36.74 58.958,37.831 58.958,38.15 59.098,38.29 59.239,38.431 U13.16@61.083,38.431 ; v1(73.262,29.517) 73.708,29.071 R24.1@73.708,28.425
  Bottom Layer w0.152: v1(59.883,34.346) 60.553,33.676 67.836,33.676 67.856,33.696 68.294,33.696 68.314,33.676 69.103,33.676 v1(73.262,29.517)
NetC31_1: C31.1 U7.14 Y1.1 | length 6.2
  Top Layer w0.3: U7.14@68.283,22.5 69.658,22.5 Y1.1@71.208,20.95 73.458,20.95 C31.1@73.708,20.7
NetC32_1: C32.1 U7.16 Y1.2 | length 6.2
  Top Layer w0.3: U7.16@68.283,23.5 69.658,23.5 Y1.2@71.208,25.05 73.444,25.05 C32.1@73.708,25.314
NetC34_1: C34.1 U14.4 | length 2.5
  Top Layer w0.152: C34.1@36.616,48.864 37.458,49.705 37.458,50.448 37.567,50.556 U14.4@37.966,50.556
NetC34_2: C34.2 L1.1 U14.3 U14.12 | length 5.2
  Top Layer w0.152: C34.2@36.616,50.464 37.209,51.056 U14.3@37.966,51.056 38.69,51.056 U14.12@38.866,51.233
  Top Layer w0.3: U14.12@38.866,51.233 U14.12@38.866,52.019 L1.1@38.866,53.905
NetC38_2: C38.2 R31.2 R33.1 U14.7 | length 5.4
  Top Layer w0.152: U14.7@39.366,49.831 40.743,49.831 R31.2@41.066,50.155 41.066,48.822 R33.1@41.126,48.762 ; R33.1@41.07,48.707 42.457,47.319 C38.2@42.457,47.107
NetC42_1: C42.1 U14.5 | length 1.3
  Top Layer w0.152: C42.1@38.066,48.655 38.366,48.955 U14.5@38.366,49.831
NetC43_1: C43.1 R32.1 | length 2.2
  Top Layer w0.5: C43.1@54.632,51.155 55.116,51.639 R32.1@55.116,53.105
NetC51_1: C51.1 U21.8 | length 2.1
  Top Layer w0.254: C51.1@15.308,48.063 15.495,48.25 16.186,48.25 16.266,48.329 16.746,48.329 16.825,48.25 U21.8@17.308,48.25
NetC51_2: C51.2 R51.1 R54.2 R55.2 U21.5 U21.11
  other v2: 18.708,47.3 18.133,48.25 19.283,48.25 18.708,49.2
NetD1_1_2: D1_1.2 R6_1.1 | length 1.6
  Top Layer w0.152: D1_1.2@43.06,39.275 43.548,38.787 R6_1.1@44.431,38.787
NetD1_2_2: D1_2.2 R6_2.1 | length 1.6
  Top Layer w0.152: D1_2.2@43.06,34.297 43.548,33.808 R6_2.1@44.431,33.808
NetD1_3_2: D1_3.2 R6_3.1 | length 1.6
  Top Layer w0.152: D1_3.2@43.06,29.318 43.548,28.83 R6_3.1@44.431,28.83
NetD1_4_2: D1_4.2 R6_4.1 | length 1.6
  Top Layer w0.152: D1_4.2@43.06,24.34 43.548,23.851 R6_4.1@44.431,23.851
NetD1_5_2: D1_5.2 R6_5.1 | length 1.6
  Top Layer w0.152: D1_5.2@42.959,17.754 43.447,17.266 R6_5.1@44.33,17.266
NetD1_6_2: D1_6.2 R6_6.1 | length 1.6
  Top Layer w0.152: D1_6.2@42.959,12.775 43.447,12.287 R6_6.1@44.33,12.287
NetD1_7_2: D1_7.2 R6_7.1 | length 1.6
  Top Layer w0.152: D1_7.2@42.959,7.775 43.448,7.287 R6_7.1@44.331,7.287
NetD1_8_2: D1_8.2 R6_8.1 | length 1.6
  Top Layer w0.152: D1_8.2@42.959,2.775 43.447,2.287 R6_8.1@44.33,2.287
NetD2_1: D2.1 R21.1 U11.3 | length 10.3
  Top Layer w0.152: R21.1@48.266,36.171 48.266,34.6 49.17,33.696 50,33.696 ; D2.1@49.939,32.729 49.939,33.635 50,33.696 ; U11.3@55.118,34.84 54.53,34.253 51.107,34.253 50.551,33.696 50,33.696
NetD2_2: D2.2 R22.2 | length 2.2
  Top Layer w0.152: D2.2@49.941,34.722 51.465,34.722 R22.2@51.81,35.067 ; R22.2@51.81,35.171 R22.2@52.046,35.171
NetD3_1: D3.1 R8.2 | length 45.5
  Top Layer w0.152: D3.1@55.926,43.457 56.219,43.75 v1(56.958,43.75) 56.958,43.552 v1@56.906,43.5 ; R8.2@72.124,13.93 73.165,13.93 v1(73.208,13.887)
  Bottom Layer w0.152: v1(56.958,43.75) 56.958,43.034 56.391,42.467 56.391,41.43 58.098,39.723 58.098,35.36 60.903,32.555 67.159,32.555 67.219,32.495 67.655,32.495 67.715,32.555 69.396,32.555 73.708,28.243 73.708,16.137 72.992,15.421 72.989,15.421 72.679,15.111 72.679,14.416 v1(73.208,13.887)
NetD3_2: D3.2 R16.2 U8.8 U10.1 | length 7.6
  Top Layer w0.152: U10.1@51.475,37.65 52.174,37.65 53.575,39.051 U8.8@53.575,39.15 54.025,39.6 54.708,39.6 R16.2@56.108,41 56.108,42.275 D3.2@55.926,42.457
NetD4_2: D4.2 U6.5 U6.7 | length 3.2
  Top Layer w0.152: U6.5@54.525,44.3 55.797,44.3 D4.2@55.924,44.427 55.051,45.3 U6.7@54.525,45.3
NetD6_1: D6.1 R40.2 R44.1 U19.4 | length 5.9
  Top Layer w0.152: D6.1@62.953,52.147 62.953,53.516 R40.2@62.823,53.646 63.206,53.646 U19.4@64.073,54.513 63.548,55.038 63.548,56.392 R44.1@63.082,56.858
NetD8_1: D8.1 U24.1 | length 2.2
  Top Layer w0.152: D8.1@26.808,57.55 27.958,58.7 U24.1@28.55,58.7
NetD8_2: D8.2 R61.2 | length 3
  Top Layer w0.152: D8.2@26.808,55.95 28.069,54.69 R61.2@29.258,54.69
NetD9_1: D9.1 R64.2 | length 1.6
  Top Layer w0.152: R64.2@45.818,2.3 47.097,2.3 D9.1@47.333,2.536
NetD9_2: D9.2 U23.4 | length 3.4
  Top Layer w0.152: D9.2@47.333,4.136 47.602,4.136 48.234,4.768 49.239,4.768 49.618,5.147 U23.4@50.319,5.147
NetJ2_2: J2.2 R17.2 U8.5 | length 5
  Top Layer w0.152: R17.2@50.029,42.107 50.029,40.603 J2.2@49.401,39.974 50.323,39.974 51.147,39.15 U8.5@51.625,39.15
NetL2_1: L2.1 U15.1 | length 7
  Top Layer w0.3: 49.116,55.66 49.116,50.174 50.135,49.155 U15.1@50.216,49.155
NetL3_1: L3.1 U16.2 | length 1.7
  Top Layer w0.254: L3.1@59.35,58.174 60.366,57.158 U16.2@60.366,56.906
NetQ1_1: Q1.1@23.616,55.75 R35.1 R36.1 | length 3
  Top Layer w0.2: R35.1@23.616,54.3 Q1.1@23.616,55.75
  Top Layer w0.3: R35.1@23.616,54.3 24.966,54.3 R36.1@25.116,54.45
NetR1_1_2: R1_1.2 U1_1.4 | length 1.5
  Top Layer w0.152: R1_1.2@37.752,38.714 38.488,39.45 U1_1.4@38.935,39.45
NetR1_2_2: R1_2.2 U1_2.4 | length 1.5
  Top Layer w0.152: R1_2.2@37.752,33.735 38.488,34.471 U1_2.4@38.935,34.471
NetR1_3_2: R1_3.2 U1_3.4 | length 1.5
  Top Layer w0.152: R1_3.2@37.752,28.757 38.488,29.493 U1_3.4@38.935,29.493
NetR1_4_2: R1_4.2 U1_4.4 | length 1.5
  Top Layer w0.152: R1_4.2@37.752,23.778 38.488,24.514 U1_4.4@38.935,24.514
NetR1_5_2: R1_5.2 U1_5.4 | length 1.5
  Top Layer w0.152: R1_5.2@37.652,17.192 38.388,17.928 U1_5.4@38.835,17.928
NetR1_6_2: R1_6.2 U1_6.4 | length 1.5
  Top Layer w0.152: R1_6.2@37.652,12.214 38.388,12.95 U1_6.4@38.835,12.95
NetR1_7_2: R1_7.2 U1_7.4 | length 1.5
  Top Layer w0.152: R1_7.2@37.652,7.214 38.388,7.95 U1_7.4@38.835,7.95
NetR1_8_2: R1_8.2 U1_8.4 | length 1.5
  Top Layer w0.152: R1_8.2@37.652,2.214 38.388,2.95 U1_8.4@38.835,2.95
NetR2_1_1: R2_1.1 R3_1.2 U3_1.4 U3_1.5 U3_1.6 U4_1.4 U4_1.5 U4_1.6 | length 4.8
  Top Layer w0.152: 21.299,40.236 22.434,40.236 R3_1.2@22.747,40.55 ; R3_1.2@22.748,40.971 R3_1.2@22.748,41.021
  Top Layer w0.5: R2_1.1@18.108,40.236 21.299,40.236
NetR2_2_1: R2_2.1 R3_2.2 U3_2.4 U3_2.5 U3_2.6 U4_2.4 U4_2.5 U4_2.6 | length 4.8
  Top Layer w0.152: 21.299,35.258 22.434,35.258 R3_2.2@22.747,35.571 ; R3_2.2@22.748,35.992 R3_2.2@22.748,36.043
  Top Layer w0.5: R2_2.1@18.108,35.258 21.299,35.258
NetR2_3_1: R2_3.1 R3_3.2 U3_3.4 U3_3.5 U3_3.6 U4_3.4 U4_3.5 U4_3.6 | length 4.8
  Top Layer w0.152: 21.299,30.279 22.434,30.279 R3_3.2@22.747,30.593 ; R3_3.2@22.748,31.014 R3_3.2@22.748,31.064
  Top Layer w0.5: R2_3.1@18.108,30.279 21.299,30.279
NetR2_4_1: R2_4.1 R3_4.2 U3_4.4 U3_4.5 U3_4.6 U4_4.4 U4_4.5 U4_4.6 | length 4.8
  Top Layer w0.152: 21.299,25.301 22.434,25.301 R3_4.2@22.747,25.614 ; R3_4.2@22.748,26.035 R3_4.2@22.748,26.085
  Top Layer w0.5: R2_4.1@18.108,25.301 21.299,25.301
NetR2_5_1: R2_5.1 R3_5.2 U3_5.4 U3_5.5 U3_5.6 U4_5.4 U4_5.5 U4_5.6 | length 4.8
  Top Layer w0.152: 21.199,18.715 22.333,18.715 R3_5.2@22.647,19.028 ; R3_5.2@22.647,19.449 R3_5.2@22.647,19.5
  Top Layer w0.5: R2_5.1@18.008,18.715 21.199,18.715
NetR2_6_1: R2_6.1 R3_6.2 U3_6.4 U3_6.5 U3_6.6 U4_6.4 U4_6.5 U4_6.6 | length 4.8
  Top Layer w0.152: 21.199,13.736 22.333,13.736 R3_6.2@22.647,14.05 ; R3_6.2@22.647,14.471 R3_6.2@22.647,14.521
  Top Layer w0.5: R2_6.1@18.008,13.736 21.199,13.736
NetR2_7_1: R2_7.1 R3_7.2 U3_7.4 U3_7.5 U3_7.6 U4_7.4 U4_7.5 U4_7.6 | length 4.8
  Top Layer w0.152: 21.199,8.736 22.334,8.736 R3_7.2@22.647,9.05 ; R3_7.2@22.647,9.471 R3_7.2@22.647,9.521
  Top Layer w0.5: R2_7.1@18.008,8.736 21.199,8.736
NetR2_8_1: R2_8.1 R3_8.2 U3_8.4 U3_8.5 U3_8.6 U4_8.4 U4_8.5 U4_8.6 | length 4.8
  Top Layer w0.152: 21.199,3.736 22.333,3.736 R3_8.2@22.647,4.05 ; R3_8.2@22.647,4.471 R3_8.2@22.647,4.521
  Top Layer w0.5: R2_8.1@18.008,3.736 21.199,3.736
NetR4_1_1: R4_1.1 U2_1.3 U2_1.4 | length 8.9
  Top Layer w0.152: U2_1.3@32.529,38.361 U2_1.4@34.779,38.361 35.178,37.963 36.766,37.963 36.928,38.124 36.928,39.574 37.149,39.795 38.386,39.795 R4_1.1@39.267,40.675
NetR4_2_1: R4_2.1 U2_2.3 U2_2.4 | length 8.9
  Top Layer w0.152: U2_2.3@32.529,33.383 U2_2.4@34.779,33.383 35.178,32.984 36.766,32.984 36.928,33.146 36.928,34.595 37.149,34.816 38.386,34.816 R4_2.1@39.267,35.696
NetR4_3_1: R4_3.1 U2_3.3 U2_3.4 | length 8.9
  Top Layer w0.152: U2_3.3@32.529,28.404 U2_3.4@34.779,28.404 35.178,28.005 36.766,28.005 36.928,28.167 36.928,29.617 37.149,29.838 38.386,29.838 R4_3.1@39.267,30.718
NetR4_4_1: R4_4.1 U2_4.3 U2_4.4 | length 8.9
  Top Layer w0.152: U2_4.3@32.529,23.426 U2_4.4@34.779,23.426 35.178,23.027 36.766,23.027 36.928,23.189 36.928,24.638 37.149,24.859 38.386,24.859 R4_4.1@39.267,25.739
NetR4_5_1: R4_5.1 U2_5.3 U2_5.4 | length 8.9
  Top Layer w0.152: U2_5.3@32.429,16.84 U2_5.4@34.679,16.84 35.077,16.441 36.666,16.441 36.828,16.603 36.828,18.052 37.049,18.273 38.286,18.273 R4_5.1@39.166,19.153
NetR4_6_1: R4_6.1 U2_6.3 U2_6.4 | length 8.9
  Top Layer w0.152: U2_6.3@32.429,11.861 U2_6.4@34.679,11.861 35.077,11.463 36.666,11.463 36.828,11.624 36.828,13.074 37.049,13.295 38.286,13.295 R4_6.1@39.166,14.175
NetR4_7_1: R4_7.1 U2_7.3 U2_7.4 | length 8.9
  Top Layer w0.152: U2_7.3@32.429,6.861 U2_7.4@34.679,6.861 35.078,6.463 36.666,6.463 36.828,6.625 36.828,8.074 37.049,8.295 38.286,8.295 R4_7.1@39.166,9.175
NetR4_8_1: R4_8.1 U2_8.3 U2_8.4 | length 8.9
  Top Layer w0.152: U2_8.3@32.429,1.861 U2_8.4@34.679,1.861 35.077,1.463 36.666,1.463 36.828,1.624 36.828,3.074 37.049,3.295 38.286,3.295 R4_8.1@39.166,4.175
NetR5_1_1: R5_1.1 R7_1.2 U5_1.1 U5_1.2 | length 6.1
  Top Layer w0.152: R5_1.1@24.35,40.971 24.999,40.971 25.858,40.111 U5_1.1@25.858,39.45 U5_1.2@27.758,39.45 28.751,39.45 R7_1.2@29.251,38.95
NetR5_2_1: R5_2.1 R7_2.2 U5_2.1 U5_2.2 | length 6.1
  Top Layer w0.152: R5_2.1@24.35,35.992 24.999,35.992 25.858,35.133 U5_2.1@25.858,34.471 U5_2.2@27.758,34.471 28.751,34.471 R7_2.2@29.251,33.971
NetR5_3_1: R5_3.1 R7_3.2 U5_3.1 U5_3.2 | length 6.1
  Top Layer w0.152: R5_3.1@24.35,31.014 24.999,31.014 25.858,30.154 U5_3.1@25.858,29.493 U5_3.2@27.758,29.493 28.751,29.493 R7_3.2@29.251,28.993
NetR5_4_1: R5_4.1 R7_4.2 U5_4.1 U5_4.2 | length 6.1
  Top Layer w0.152: R5_4.1@24.35,26.035 24.999,26.035 25.858,25.176 U5_4.1@25.858,24.514 U5_4.2@27.758,24.514 28.751,24.514 R7_4.2@29.251,24.014
NetR5_5_1: R5_5.1 R7_5.2 U5_5.1 U5_5.2 | length 6.1
  Top Layer w0.152: R5_5.1@24.25,19.449 24.899,19.449 25.758,18.59 U5_5.1@25.758,17.928 U5_5.2@27.658,17.928 28.65,17.928 R7_5.2@29.15,17.428
NetR5_6_1: R5_6.1 R7_6.2 U5_6.1 U5_6.2 | length 6.1
  Top Layer w0.152: R5_6.1@24.25,14.471 24.899,14.471 25.758,13.611 U5_6.1@25.758,12.95 U5_6.2@27.658,12.95 28.65,12.95 R7_6.2@29.15,12.45
NetR5_7_1: R5_7.1 R7_7.2 U5_7.1 U5_7.2 | length 6.1
  Top Layer w0.152: R5_7.1@24.25,9.471 24.899,9.471 25.758,8.611 U5_7.1@25.758,7.95 U5_7.2@27.658,7.95 28.65,7.95 R7_7.2@29.15,7.45
NetR5_8_1: R5_8.1 R7_8.2 U5_8.1 U5_8.2 | length 6.1
  Top Layer w0.152: R5_8.1@24.25,4.471 24.899,4.471 25.758,3.611 U5_8.1@25.758,2.95 U5_8.2@27.658,2.95 28.65,2.95 R7_8.2@29.15,2.45
NetR15_1: R15.1 U8.2 | length 3.8
  Top Layer w0.152: R15.1@50.029,43.72 50.362,43.72 50.801,43.281 51.613,43.281 52.409,42.485 52.696,42.485 52.925,42.256 U8.2@52.925,41.95
NetR19_1: R19.1 U8.7 U10.3 | length 6
  Top Layer w0.152: U10.3@51.475,36.35 50.129,36.35 50.029,36.45 50.732,37.154 50.732,37.979 51.024,38.27 52.145,38.27 52.925,39.051 U8.7@52.925,39.15
NetR21_2: R21.2 R22.1 U10.4 | length 8.8
  Top Layer w0.152: R21.2@48.266,37.771 49.116,36.921 49.116,35.65 49.321,35.445 50.517,35.445 50.93,35.858 52.619,35.858 R22.1@53.41,35.067 53.725,35.382 U10.4@53.725,36.35
NetR26_1: R26.1 R27.1 U7.34 | length 19.8
  Top Layer w0.152: R26.1@58.908,43.25 58.792,43.25 v1(58.058,43.984) 58.8,44.727 R27.1@58.914,44.727 ; v1(61.836,37.287) 61.836,36.537 62.254,36.119 62.254,31.123 62.458,30.919 U7.34@62.458,29.825
  Bottom Layer w0.152: v1(58.058,43.984) 58.06,43.986 60.652,43.986 61.836,42.802 v1(61.836,37.287)
NetR27_2: R27.2 U13.11 | length 2.8
  Top Layer w0.152: R27.2@58.933,46.1 59.349,46.1 60.719,44.73 U13.11@61.133,44.73
NetR29_2: R29.2 U14.8 U15.7 | length 20.6
  Top Layer w0.152: U14.8@39.766,50.556 40.169,50.556 40.765,51.152 44.466,51.152 v1(44.643,51.329) ; U15.7@53.016,47.655 54.055,47.655 R29.2@54.208,47.502 54.98,47.502 v1(55.208,47.73)
  Bottom Layer w0.152: v1(44.643,51.329) 44.819,51.152 53.44,51.152 55.208,49.384 v1(55.208,47.73)
NetR30_2: R30.2 U15.6 U16.5 | length 17.2
  Top Layer w0.152: U15.6@53.016,47.155 53.458,46.713 v1(53.458,46.5) ; R30.2@56.666,54.69 56.691,54.665 v1@56.691,53.713 ; v1@60.366,55.616 U16.5@60.366,56.306
  Bottom Layer w0.152: v1(53.458,46.5) 54.725,46.5 55.737,47.511 55.737,49.643 55.38,50 55.38,53.394 55.733,53.747 56.658,53.747 56.691,53.713 56.725,53.747 58.497,53.747 v1@60.366,55.616
  other v1: 56.683,53.742 60.184,55.539
NetR34_1: R34.1 U15.5 | length 1
  Top Layer w0.254: R34.1@49.258,47.155 U15.5@50.216,47.155
NetR41_2: R41.2 R43.1 U18.4 | length 2.6
  Top Layer w0.254: R41.2@44.217,48.45 R41.2@44.467,48.2 ; U18.4@44.683,47.255 44.683,47.984 R41.2@44.467,48.2 ; R43.1@45.708,48.2 R41.2@44.467,48.2
NetR43_2: R43.2 R47.1 U18.3 | length 2.8
  Top Layer w0.254: U18.3@44.683,46.055 45.163,46.055 R43.2@45.708,46.6 R47.1@45.708,45.05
